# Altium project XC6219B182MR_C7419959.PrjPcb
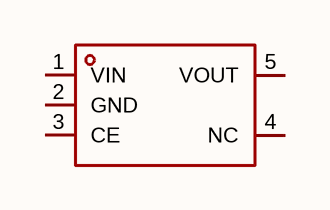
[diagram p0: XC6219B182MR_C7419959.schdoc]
1 sheet, 1 parts. Net scope: global (net labels, ports and power ports of the same name join across sheets).

## Sheet XC6219B182MR_C7419959.schdoc
size 127 x 101 mm

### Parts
U?  xc6219b182mr_c7419959  [SOT-23-5_L2.9-W1.6-P0.95-LS2.8-BR]  (value not drawn)

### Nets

Not connected (* = marked no-connect by the designer): U? 1(VIN) 2(GND) 3(CE) 4(NC) 5(VOUT)

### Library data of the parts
U? = xc6219b182mr_c7419959: 输出极性:正极;工作电压:6V;输出电压:1.8V;输出电流:300mA;电源纹波抑制比(PSRR):70dB@(1kHz);输出类型:固定;; Manufacturer: TECH PUBLIC(台舟); AddInBom: yes; ModelId: 7ba65df16e7b4570af156e925f9c37fe; ModelTransform: 114.173,114.173,0,90,0,0,0,0,0; Output Configuration: 正极; Voltage - Supply: 6V; Output Voltage: 1.8V; Output Current: 300mA; Voltage Dropout: 90mV@(100mA)；230mV@(200mA); standby current: 70uA; Noise: 50uVrms; Output Type: 固定; Number of Outputs: 1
